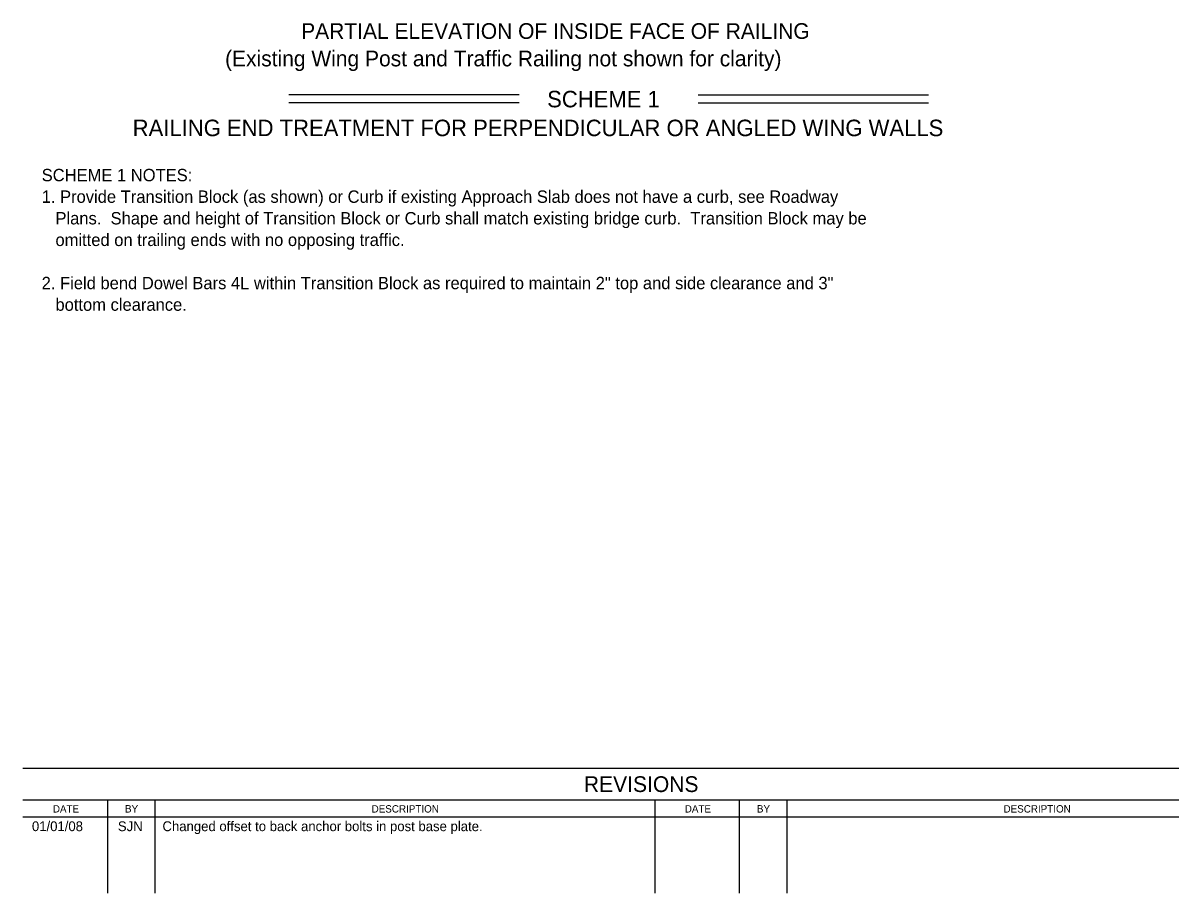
# Model space of a CAD drawing. Extents: x 21526.6 to 21598.7, y 56118.1 to 56155.9.
# Drawn here: x 21526.6 to 21545.31, y 56118.09 to 56132.27 of the extents above; entities that cross this region are included whole.
import ezdxf

# ---------------------------------------------------------------- set-up
doc = ezdxf.new("R2010")
doc.units = 0
doc.layers.add('Border', color=7, linetype='Continuous')
doc.layers.add('PlotBorder_dp', color=7, linetype='Continuous')

msp = doc.modelspace()

# ---------------------------------------------------------------- linework, layer by layer
at = {"layer": 'Border'}
for p, q in [((21547.212, 56120.12), (21526.6, 56120.12)), ((21547.212, 56119.605), (21526.6, 56119.605)), ((21527.977, 56119.605), (21527.977, 56118.09)), ((21528.751, 56119.605), (21528.751, 56118.09)), ((21536.907, 56119.605), (21536.907, 56118.09)), ((21538.283, 56119.605), (21538.283, 56118.09)), ((21539.057, 56119.605), (21539.057, 56118.09)), ((21526.6, 56119.332), (21547.212, 56119.332))]:
    msp.add_line(p, q, dxfattribs=at)
at = {"layer": 'PlotBorder_dp'}
for p, q in [((21534.695, 56131.105), (21530.937, 56131.105)), ((21534.695, 56130.972), (21530.937, 56130.972)), ((21537.611, 56131.105), (21541.369, 56131.105)), ((21537.611, 56130.972), (21541.369, 56130.972))]:
    msp.add_line(p, q, dxfattribs=at)

# ---------------------------------------------------------------- texts
at = {"layer": 'Border'}
for s, height, p in [('REVISIONS', 0.2567, (21535.749, 56119.737)), ('BY', 0.1201, (21528.265, 56119.403)), ('BY', 0.1201, (21538.571, 56119.403)), ('01/01/08', 0.16, (21526.747, 56119.099)), ('SJN', 0.16, (21528.149, 56119.099)), ('Changed offset to back anchor bolts in post base plate.', 0.16, (21528.876, 56119.099))]:
    msp.add_text(s, height=height, dxfattribs=at).set_placement(p)
for s, height, rotation, p in [('DATE', 0.1196, 359.8693, (21527.089, 56119.403)), ('DESCRIPTION', 0.12007, 0.0498, (21532.287, 56119.402)), ('DATE', 0.1196, 359.8693, (21537.395, 56119.403)), ('DESCRIPTION', 0.12007, 0.0498, (21542.593, 56119.402))]:
    msp.add_text(s, height=height, rotation=rotation, dxfattribs=at).set_placement(p)
at = {"layer": 'PlotBorder_dp'}
for s, height, p in [('PARTIAL ELEVATION OF INSIDE FACE OF RAILING', 0.256, (21531.138, 56132.015)), ('(Existing Wing Post and Traffic Railing not shown for clarity)', 0.256, (21529.897, 56131.567)), ('SCHEME 1', 0.2688, (21535.15, 56130.899)), ('RAILING END TREATMENT FOR PERPENDICULAR OR ANGLED WING WALLS', 0.2688, (21528.39, 56130.429)), ('SCHEME 1 NOTES:', 0.2016, (21526.906, 56129.694)), ('1. Provide Transition Block (as shown) or Curb if existing Approach Slab does not have a curb, see Roadway ', 0.2016, (21526.906, 56129.342)), ('   Plans.  Shape and height of Transition Block or Curb shall match existing bridge curb.  Transition Block may be ', 0.2016, (21526.906, 56128.99)), ('   omitted on trailing ends with no opposing traffic.', 0.2016, (21526.906, 56128.638)), ('2. Field bend Dowel Bars 4L within Transition Block as required to maintain 2" top and side clearance and 3" ', 0.2016, (21526.906, 56127.934)), ('   bottom clearance.', 0.2016, (21526.906, 56127.582))]:
    msp.add_text(s, height=height, dxfattribs=at).set_placement(p)

doc.saveas('drawing.dxf')
